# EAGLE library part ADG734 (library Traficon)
CMOS, 2.5 Low Voltage, Triple/Quad SPDT Switches
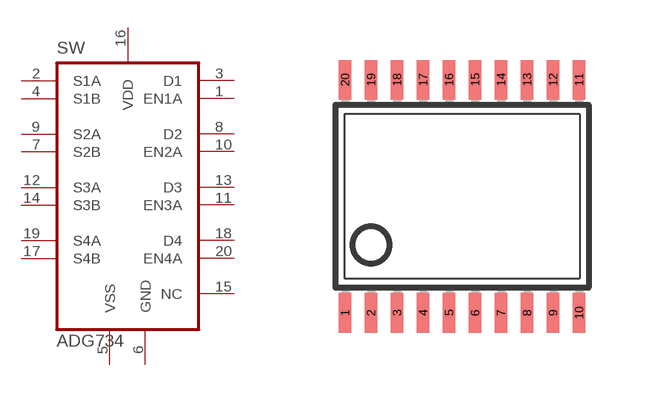
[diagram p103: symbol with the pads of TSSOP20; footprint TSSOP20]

Designator prefix SW

## ADG734BRU  [TSSOP20]
1  EN1A
2  S1A
3  D1
4  S1B
5  VSS
6  GND
7  S2B
8  D2
9  S2A
10  EN2A
11  EN3A
12  S3A
13  D3
14  S3B
15  NC  nc
16  VDD
17  S4B
18  D4
19  S4A
20  EN4A

## Footprint TSSOP20 (pad centres in mm)
Thin Shrink Small Outline Plastic 20 MAX3223-MAX3243.pdf
smd 0.305 x 0.991: 1 -2.925,-2.918; 2 -2.275,-2.918; 3 -1.625,-2.918; 4 -0.975,-2.918; 5 -0.325,-2.918; 6 0.325,-2.918; 7 0.975,-2.918; 8 1.625,-2.918; 9 2.275,-2.918; 10 2.925,-2.918; 11 2.925,2.918; 12 2.275,2.918; 13 1.625,2.918; 14 0.975,2.918; 15 0.325,2.918; 16 -0.325,2.918; 17 -0.975,2.918; 18 -1.625,2.918; 19 -2.275,2.918; 20 -2.925,2.918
